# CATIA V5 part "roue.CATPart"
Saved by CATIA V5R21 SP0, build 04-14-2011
Part number: roue
Revision: A
Nomenclature: 3
Material "Aluminium": density 2710 kg/m3, Young's modulus 7e+10 Pa, Poisson ratio 0.346, thermal expansion 2.36e-05 1/K
Bounding box of the stored display mesh (mm): x -36.5 to 20, y -31 to 31, z -31 to 31
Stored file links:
  C:\Users\Olivier\Desktop\redaction CATIA (local)\CATIA\DONNEES\Exercice assemblage 1 (chassis et socle)\Assemblage chassis et socle (Product inclus)\roue.CATPart
  C:\Program Files\Dassault Systemes\B21\win_b64\startup\materials\French\Catalog.CATMaterial
  C:\Users\Olivier\Desktop\redaction CATIA (local)\CATIA\DONNEES\Exercice assemblage 1 (chassis et socle)\Assemblage chassis et socle (Product inclus)\CATIA_EnvironmentMap_Satin_512x512.jpg
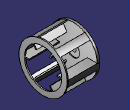
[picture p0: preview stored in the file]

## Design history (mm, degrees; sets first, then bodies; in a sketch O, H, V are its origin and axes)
Body1 (main body), material "Aluminium"
  Sketch1 on yz-plane, origin (0, 0, 0), H (0, 1, 0), V (0, 0, 1)
    arc A1 centre (0, 0) radius 31 from (21.7261, 22.1128) to (14.8459, 27.2139) ccw
    arc A2 centre (0, 0) radius 29.5 from (20.6749, 21.0428) to (15.3948, 25.1645) ccw
    line L1 (9.6319, 15.1829) -> (15.3948, 25.1645)
    line L2 (8.3328, 15.9329) -> (14.8459, 27.2139)
    construction line L3 (0, 0) -> (-1.299, 0.75)
    line L4 (20.6749, 21.0428) -> (21.7261, 22.1128)
    arc A3 centre (0, 0) radius 17.9804 from (9.6319, 15.1829) to (8.3328, 15.9329) ccw
    angle L1 H = 60
    distance L1 L2 = 1.5
    distance A1 A2 = 1.5
    radius A1 = 31
    perpendicularity: L3 L1, L3 L2
  Pad1: profile Sketch1, direction (1, 0, 0), length 20, mirrored extent
  Sketch2 on start face of Pad1, origin (-20, 0, 0), H (0, -1, 0), V (0, 0, 1)
    reference projected arc E1 centre (0, 0) radius 31 from (-14.8459, 27.2139) to (-21.7261, 22.1128) ccw from edge [start face of Pad1 | face of Pad1 from Sketch1.A1]
    circle A1 centre (0, 0) radius 31
    point P3 (-17.8616, 25.337)
    circle A2 centre (0, 0) radius 2.5
    circle A3 centre (0, 0) radius 8
    radius A2 = 2.5
    radius A3 = 8
    coincidence: A1 P3, P3 E1
  Sketch3 on end face of Pad1, origin (20, 0, 0), H (0, 1, 0), V (0, 0, 1)
    circle A1 centre (0, 0) radius 24
    circle A2 centre (0, 0) radius 31
    radius A1 = 24
    radius A2 = 31
  Pad2: profile Sketch3, direction (-1, 0, 0), length 1.5
  MultiPad1: profile Sketch2, domains (length 16.5; length 0; length 2 / length 1)
  Sketch4 on face of MultiPad1, origin (-36.5, 0, 0), H (0, -1, 0), V (0, 0, 1)
    circle A1 centre (0, 0) radius 4.5
  Pocket1: profile Sketch4, direction (1, 0, 0), length 12
  CircPattern1: of Pad1, instances 6, angular step 60, axis from end face of Pad2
